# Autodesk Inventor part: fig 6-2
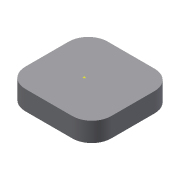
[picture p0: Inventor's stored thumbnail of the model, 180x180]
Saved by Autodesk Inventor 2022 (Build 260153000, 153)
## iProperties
Created: 2004-05
Part Number: fig 6-2
Document SubType Name: Modeling
Designer: CADCIM Technologies
Manufacturer: Standard
Standards Organization: Custom
Density: 1 g/cm^3
Material: Generic
Appearance: Default
Author: CADCIM Technologies
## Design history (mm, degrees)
sketch "Sketch1"
  geometry: L1 (0, 0)-(44.293, 0); L2 (44.293, 0)-(44.293, 42.442); L3 (44.293, 42.442)-(0, 42.442); L4 (0, 42.442)-(0, 0)
  constraints: 8 end point, 2 parallel, 1 horizontal, 1 perpendicular
extrude "Extrusion1" new body sketch "Sketch1" distance "d0" = 10; taper "d1" = 0 deg
fillet "Fillet1" dims "d2" = 10
sketch "Sketch2"
  geometry: 1 further point
sketch "Sketch3"
  geometry: L1 (10, 42.442)-(34.293, 42.442) reference; L2 (0, 10)-(0, 32.442) reference; L3 (34.293, 0)-(10, 0) reference; L4 (44.293, 32.442)-(44.293, 10) reference; A1 r 10 centre (34.293, 32.442) between (44.293, 32.442) and (34.293, 42.442) reference; A2 r 10 centre (10, 32.442) between (10, 42.442) and (0, 32.442) reference; A3 r 10 centre (10, 10) between (0, 10) and (10, 0) reference; A4 r 10 centre (34.293, 10) between (34.293, 0) and (44.293, 10) reference; 1 further point
workpoint "Work Point1"
body "Solid1"
